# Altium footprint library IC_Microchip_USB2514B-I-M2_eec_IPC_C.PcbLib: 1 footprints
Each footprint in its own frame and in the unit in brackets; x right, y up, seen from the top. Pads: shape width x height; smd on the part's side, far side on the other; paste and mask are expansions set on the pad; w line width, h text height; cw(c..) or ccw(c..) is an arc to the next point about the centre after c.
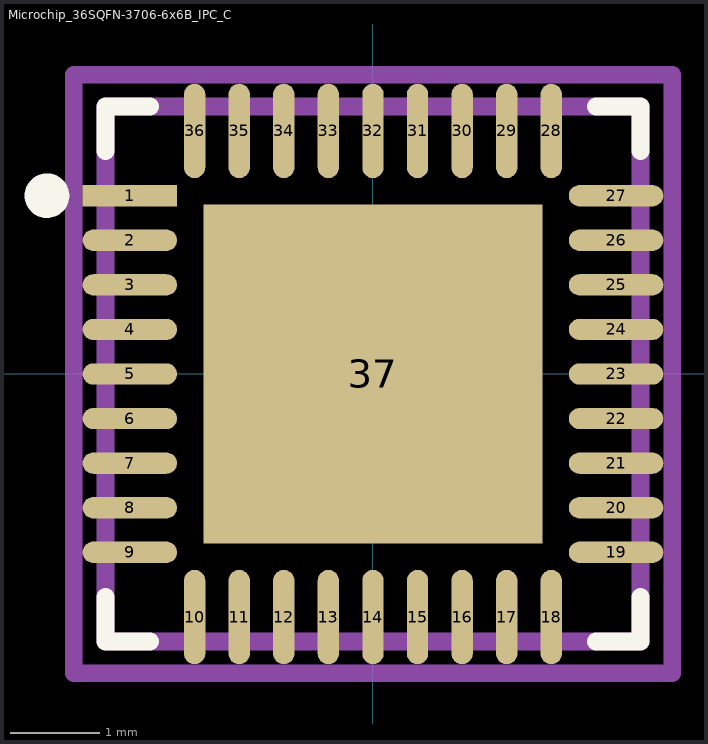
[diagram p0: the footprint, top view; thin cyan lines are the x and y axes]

## Microchip_36SQFN-3706-6x6B_IPC_C [mm]
pads (37):
  rect 1.059x0.239 smd paste+0 mask+0: 1(-2.727,2)
  rrect100% 1.059x0.239 smd paste+0 mask+0: 2(-2.727,1.5) 3(-2.727,1) 4(-2.727,0.5) 5(-2.727,0) 6(-2.727,-0.5) 7(-2.727,-1) 8(-2.727,-1.5) 9(-2.727,-2) 19(2.727,-2) 20(2.727,-1.5) 21(2.727,-1) 22(2.727,-0.5) 23(2.727,0) 24(2.727,0.5) 25(2.727,1) 26(2.727,1.5) 27(2.727,2)
  rrect100% 0.239x1.059 smd paste+0 mask+0: 10(-2,-2.727) 11(-1.5,-2.727) 12(-1,-2.727) 13(-0.5,-2.727) 14(0,-2.727) 15(0.5,-2.727) 16(1,-2.727) 17(1.5,-2.727) 18(2,-2.727) 28(2,2.727) 29(1.5,2.727) 30(1,2.727) 31(0.5,2.727) 32(0,2.727) 33(-0.5,2.727) 34(-1,2.727) 35(-1.5,2.727) 36(-2,2.727)
  rect 3.8x3.8 smd paste-1000 mask+0: 37(0,0)
Top Overlay:
  circle w0.25: c-3.656,2 r0.125
  lines w0.2: -3,-2.5 -3,-3 -2.5,-3 ; -3,2.5 -3,3 -2.5,3 ; 2.5,-3 3,-3 3,-2.5 ; 2.5,3 3,3 3,2.5
Top Paste:
  rectangle: -1.202,-1.202 1.202,1.202
Mechanical 10:
  lines w0.2: -3.356,-3.356 3.356,-3.356 3.356,3.356 -3.356,3.356 -3.356,-3.356
  text ".Designator" at 0,0.188 h1
Mechanical 12:
  lines w0.2: -3,-3 3,-3 3,3 -3,3 -3,-3
Mechanical 15:
  lines w0.1: -0.5,0 0.5,0 ; 0,-0.5 0,0.5
  lines w0.2: -3.356,-3.356 3.356,-3.356 3.356,3.356 -3.356,3.356 -3.356,-3.356
3D body "IC_Microchip_USB2514B-I-M2_eec.STEP": height 0.25, standoff 0, extent -3.356,-3.356 3.356,3.356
